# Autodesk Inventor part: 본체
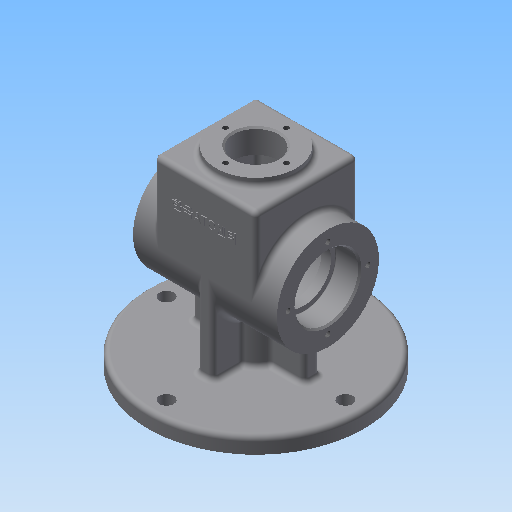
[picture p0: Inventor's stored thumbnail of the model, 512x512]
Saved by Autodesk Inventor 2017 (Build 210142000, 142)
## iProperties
Created: 2020-07
Part Number: 본체
Material: 알루미늄 6061
Document SubType Name: Modeling
Designer: mduedu
Density: 2.71 g/cm^3
Appearance: 기본값
Mass: 1025.32 g
Surface Area: 854.574 cm^2
Volume: 378.345 cm^3
Author: mduedu
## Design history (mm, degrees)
sketch "스케치1"
  geometry: C1 r 32 at (0, 0); 1 further point
  constraints: 1 centre point, 1 coincident
  dimensions: "d0" = 64 diameter of C1
extrude "돌출1" new body sketch "스케치1" stored distance "d1" = 90; taper "d2" = 0 deg
sketch "스케치3"
  geometry: L1 (0, -32)-(50, -32); L2 (50, -32)-(50, 32); L3 (50, 32)-(0, 32); L4 (0, 32)-(0, -32); C1 r 32 at (0, 0) reference; 2 further points
  constraints: 8 end point, 2 parallel, 1 coincident, 1 horizontal, 1 midpoint, 1 perpendicular, 1 tangent
  dimensions: "d5" = 50 distance of L2.end L3.end
extrude "돌출2" join sketch "스케치3" stored distance "d7" = 64; taper "d8" = 0 deg
sketch "스케치4"
  geometry: C1 r 25 at (32, 32); 1 further point
  constraints: 1 centre point, 1 coincident
  dimensions: "d9" = 50 diameter of C1
extrude "돌출3" join sketch "스케치4" distance "d10" = 5; taper "d11" = 0 deg
sketch "스케치5"
  geometry: L1 (0, -25)-(40, -25); L2 (40, -25)-(40, 25); L3 (40, 25)-(0, 25); L4 (0, 25)-(0, -25); L5 (55, -25)-(55, 25) reference; A1 r 25 centre (0, 0) between (0, 25) and (0, -25); A2 r 25 centre (0, 0) between (0, -25) and (0, 25); 2 further points
  constraints: 8 end point, 4 point on circle, 2 centre point, 2 coincident, 2 parallel, 1 horizontal, 1 midpoint, 1 perpendicular, 1 tangent
  dimensions: "d12" = 50 diameter of A1; "d13" = 15 distance between parallel lines of L2 L5
extrude "돌출4" cut sketch "스케치5" stored distance "d14" = 48; taper "d15" = 0 deg
sketch "스케치6"
  geometry: C1 r 20 at (0, 0); 1 further point
  constraints: 1 centre point, 1 coincident
  dimensions: "d16" = 40 diameter of C1
extrude "돌출5" cut sketch "스케치6" distance "d17" = 15; taper "d18" = 0 deg
sketch "스케치7"
  geometry: C1 r 17 at (0, 0); 1 further point
  constraints: 1 centre point, 1 coincident
  dimensions: "d19" = 34 diameter of C1
extrude "돌출6" cut sketch "스케치7" stored distance "d20" = 15; taper "d21" = 0 deg
fillet "모깎기1" dims "d22" = 3
fillet "모깎기2" dims "d23" = 3
fillet "모깎기3" dims "d24" = 3
fillet "모깎기4" dims "d25" = 3
fillet "모깎기5" dims "d26" = 3
sketch "스케치8"
  geometry: C1 r 14 at (0, 0); 1 further point
  constraints: 1 centre point, 1 coincident
  dimensions: "d27" = 28 diameter of C1
extrude "돌출7" cut sketch "스케치8" stored distance "d28" = 15; taper "d29" = 0 deg
node "작업 평면1"
sketch "스케치9"
  geometry: C1 r 67.5 at (0, 0); 1 further point
  constraints: 1 centre point, 1 coincident
  dimensions: "d31" = 135 diameter of C1
extrude "돌출8" join sketch "스케치9" distance "d33" = 10; taper "d34" = 0 deg
sketch "스케치10"
  geometry: C1 r 15 at (0, 0); 1 further point
  constraints: 1 centre point, 1 coincident
  dimensions: "d35" = 30 diameter of C1
extrude "돌출9" join sketch "스케치10" stored distance "d39" = 10; taper "d40" = 0 deg
sketch "스케치11"
  geometry: L1 (-35, -5)-(35, -5); L2 (35, -5)-(35, 5); L3 (35, 5)-(-35, 5); L4 (-35, 5)-(-35, -5); L5 (-35, -5)-(35, 5); L6 (35, -5)-(-35, 5); 1 further point
  constraints: 12 end point, 2 midpoint, 2 parallel, 1 horizontal, 1 perpendicular
  dimensions: "d41" = 70 distance of L3.end L2.end; "d42" = 10 distance of L2.end L1.end
extrude "돌출10" join sketch "스케치11" stored distance "d43" = 10; taper "d44" = 0 deg
sketch "스케치12"
  geometry: L1 (-5, -32)-(5, -32); L2 (5, -32)-(5, 32); L3 (5, 32)-(-5, 32); L4 (-5, 32)-(-5, -32); L5 (-5, -32)-(5, 32); L6 (5, -32)-(-5, 32); 1 further point
  constraints: 12 end point, 2 midpoint, 2 parallel, 1 horizontal, 1 perpendicular
  dimensions: "d45" = 10 distance of L3.end L2.end; "d46" = 64 distance of L2.end L1.end
extrude "돌출11" join sketch "스케치12" stored distance "d47" = 10; taper "d48" = 0 deg; dims "d12" = 50, "d13" = 15, "d27" = 28
fillet "모깎기6" dims "d50" = 3
fillet "모깎기7" dims "d51" = 3
sketch "스케치13" dims "d52" = 112
  geometry: 3 further points
  constraints: 2 horizontal alignment, 1 coincident, 2 other
hole "구멍1" sketch "스케치13" at (-56, 0) diameter "d54" = 9; stored, may be unused: countersink angle "d58" = 90 deg, drill point angle "d60" = 118 deg; dims "d55" = 6, "d56" = 4, "d57" = 2, "d59" = 8
fillet "모깎기8" dims "d64" = 3
sketch "스케치14" dims "d67" = 50
  geometry: 3 further points
  constraints: 2 vertical alignment, 1 coincident, 2 other
hole "구멍2" sketch "스케치14" at (0, 25) diameter "d68" = 3.242; stored, may be unused: countersink angle "d72" = 90 deg, drill point angle "d74" = 118 deg; dims "d69" = 7, "d70" = 4, "d71" = 2, "d73" = 9
sketch "스케치15" dims "d78" = 38
  geometry: 3 further points
  constraints: 2 vertical alignment, 1 coincident, 2 other
hole "구멍3" sketch "스케치15" at (0, 19) diameter "d79" = 3.242; stored, may be unused: countersink angle "d83" = 90 deg, drill point angle "d85" = 118 deg; dims "d80" = 8, "d81" = 4, "d82" = 2, "d84" = 10
fillet "모깎기9" dims "d89" = 0.3
chamfer "모따기1" distance "d90" = 1; stored, may be unused: second distance "d91" = 2, angle "d92" = 45 deg
chamfer "모따기2" distance "d93" = 1; stored, may be unused: second distance "d94" = 2, angle "d95" = 45 deg
sketch "스케치16"
  geometry: L1 (-3, 0)-(-3, -27.404) reference; L2 (54, 8)-(4, 8) reference; 2 further points
  constraints: 1 other
  dimensions: "d96" = 32 distance from line of point (29, -17) L1; "d97" = 25 distance from line of point (29, -17) L2
feature "엠보싱1" sketch "스케치16" dims "d0" = 64, "d98" = 0.5, "d99" = 0
node "솔리드1"
mirror "대칭1"
pattern_circular "원형 패턴1" dims angle "d62" = 360 deg
pattern_circular "원형 패턴2" dims angle "d76" = 360 deg
mirror "대칭2"
pattern_circular "원형 패턴3" dims angle "d87" = 360 deg
other parameters: "d30" = -65
